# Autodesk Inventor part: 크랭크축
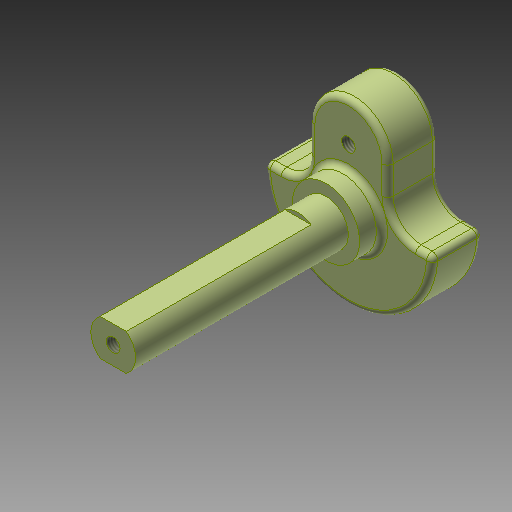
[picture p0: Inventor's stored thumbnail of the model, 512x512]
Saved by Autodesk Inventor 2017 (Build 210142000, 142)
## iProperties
Created: 2018-01
Part Number: 크랭크축
Material: 강철, 탄소
Document SubType Name: Modeling
Designer: mduedu
Density: 7.87 g/cm^3
Mass: 57.3413 g
Surface Area: 32.1344 cm^2
Volume: 7.28606 cm^3
Appearance: 아연 크롬산색 2
Author: mduedu
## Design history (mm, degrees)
sketch "스케치1"
  geometry: L1 (-15, 0)-(15, 0); L2 (-7, 0)-(7, 0); L3 (7, 0)-(7, 10); L4 (-7, 10)-(-7, 0); A1 r 15 centre (0, 0) between (-15, 0) and (15, 0); A2 r 7 centre (0, 10) between (7, 10) and (-7, 10); 3 further points
  constraints: 8 end point, 4 point on circle, 3 coincident, 2 centre point, 2 horizontal, 2 midpoint, 2 tangent, 1 parallel, 1 perpendicular, 1 point on line
  dimensions: "d0" = 30 diameter of A1; "d1" = 17 dimension on A2 L1; "d2" = 7 radius of A2
extrude "돌출1" new body sketch "스케치1" distance "d4" = 9; taper "d5" = 0 deg
sketch "스케치2"
  geometry: C1 r 6 at (0, 0); 1 further point
  constraints: 1 centre point, 1 coincident
  dimensions: "d6" = 12 diameter of C1
extrude "돌출2" join sketch "스케치2" distance "d7" = 4; taper "d8" = 0 deg
sketch "스케치3"
  geometry: C1 r 4 at (0, 0); 1 further point
  constraints: 1 centre point, 1 coincident
  dimensions: "d9" = 8 diameter of C1
extrude "돌출3" join sketch "스케치3" distance "d10" = 38; taper "d11" = 0 deg
sketch "스케치4"
  geometry: L1 (-2.332, 3.25)-(2.332, 3.25); L2 (-2.332, -3.25)-(2.332, -3.25); A1 r 4 centre (0, 0) between (-2.332, 3.25) and (2.332, 3.25) reference; A2 r 4 centre (0, 0) between (2.332, 3.25) and (-2.332, 3.25); A3 r 4 centre (0, 0) between (-2.332, -3.25) and (2.332, -3.25); 1 further point
  constraints: 8 point on circle, 4 end point, 2 centre point, 2 coincident, 2 parallel, 1 horizontal
  dimensions: "d12" = 6.5 distance between parallel lines of L2 L1
extrude "돌출4" cut sketch "스케치4" distance "d13" = 33; taper "d14" = 0 deg
fillet "모깎기1" dims "d15" = 5
fillet "모깎기2" dims "d16" = 1
fillet "모깎기3" dims "d17" = 1
fillet "모깎기4" dims "d18" = 1
sketch "스케치5"
  geometry: 1 further point
  constraints: 1 other
hole "구멍1" sketch "스케치5" at (0, 10) diameter "d19" = 2.459; stored, may be unused: countersink angle "d23" = 90 deg, drill point angle "d25" = 120 deg; dims "d20" = 10, "d21" = 4, "d22" = 2, "d24" = 11.5
sketch "스케치6"
  geometry: 1 further point
  constraints: 1 other
hole "구멍2" sketch "스케치6" at (0, 0) diameter "d26" = 2.459; stored, may be unused: countersink angle "d30" = 90 deg, drill point angle "d32" = 120 deg; dims "d27" = 12.7, "d28" = 4, "d29" = 2, "d31" = 14.2
node "솔리드1"
node "투영된 루프1"
